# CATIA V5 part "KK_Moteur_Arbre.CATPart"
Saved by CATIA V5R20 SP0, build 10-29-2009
Part number: moteur_arbre
Bounding box of the stored display mesh (mm): x -50 to 50, y -50 to 50, z 0 to 160
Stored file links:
  G:\Khaled_CFAO_2011\ST2M\ST2M_GR2\tcorbin\Khaled\CAD_ThinkMOTION\KK_Moteur_Arbre.CATPart
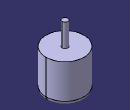
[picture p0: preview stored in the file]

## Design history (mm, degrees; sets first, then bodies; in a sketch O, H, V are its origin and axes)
Body1 (main body)
  Sketch1 on xy-plane, origin (0, 0, 0), H (1, 0, 0), V (0, 1, 0)
    circle A1 centre (0, 0) radius 50
    radius A1 = 50
  Pad1: profile Sketch1, direction (0, 0, 1), length 100
  Sketch2 on end face of Pad1, origin (0, 0, 100), H (1, 0, 0), V (0, 1, 0)
    circle A1 centre (0, 0) radius 7.5
    radius A1 = 7.5
    radius A1 = 7.5 (reference)
    radius A1 = 7.5 (reference)
  Pad2: profile Sketch2, direction (0, 0, 1), length 60
  Fillet1: radius 10, on start face of Pad1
